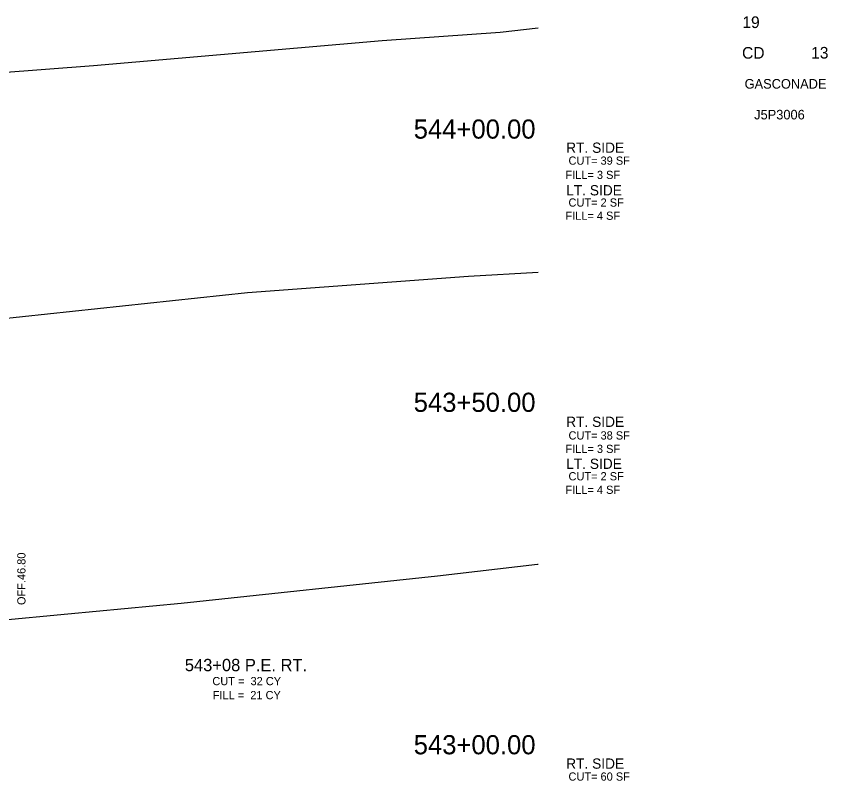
# Model space of a CAD drawing. Extents: x -4 to 359, y 0 to 1436.
# Drawn here: x 299.4 to 358.7, y 330.2 to 386.1 of the extents above; entities that cross this region are included whole.
import ezdxf

# ---------------------------------------------------------------- set-up
doc = ezdxf.new("R2010")
doc.units = 0
for name, color, linetype in [('Common-Title block info', 7, 'Continuous'), ('XS-Existing surface-ground', 7, 'Continuous'), ('XS-Text-earthwork labels', 7, 'Continuous'), ('XS-Text-offset label', 7, 'Continuous'), ('XS-Text-tie elevation', 7, 'Continuous')]:
    doc.layers.add(name, color=color, linetype=linetype)

msp = doc.modelspace()

# ---------------------------------------------------------------- linework, layer by layer
at = {"layer": 'XS-Existing surface-ground'}
for p, q in [((326.111, 384.307), (334.729, 384.919)), ((334.729, 384.919), (337.5, 385.239)), ((305.024, 382.476), (326.111, 384.307)), ((292.786, 381.565), (305.024, 382.476)), ((316.271, 365.902), (332.414, 367.082)), ((332.414, 367.082), (337.5, 367.373)), ((286.975, 362.784), (316.271, 365.902)), ((330.138, 345.194), (337.446, 346.064)), ((337.446, 346.064), (337.5, 346.068)), ((311.43, 343.207), (330.138, 345.194)), ((303.155, 342.431), (311.43, 343.207)), ((294.12, 341.584), (303.155, 342.431))]:
    msp.add_line(p, q, dxfattribs=at)

# ---------------------------------------------------------------- texts
at = {"layer": 'Common-Title block info'}
for s, height, p in [('19', 0.85, (352.417, 385.217)), ('CD', 0.85, (352.395, 382.979)), ('13', 0.85, (357.442, 382.988)), ('GASCONADE', 0.7, (352.581, 380.792)), ('J5P3006', 0.7, (353.279, 378.542))]:
    msp.add_text(s, height=height, dxfattribs=at).set_placement(p)
at = {"layer": 'XS-Text-earthwork labels'}
for s, height, p in [('RT. SIDE', 0.75, (339.547, 376.102)), (' CUT= 39 SF           ', 0.6, (339.495, 375.233)), ('FILL= 3 SF           ', 0.6, (339.495, 374.192)), ('LT. SIDE', 0.75, (339.547, 372.991)), (' CUT= 2 SF           ', 0.6, (339.495, 372.172)), ('FILL= 4 SF           ', 0.6, (339.495, 371.208)), ('RT. SIDE', 0.75, (339.547, 356.081)), (' CUT= 38 SF           ', 0.6, (339.495, 355.16)), ('FILL= 3 SF           ', 0.6, (339.495, 354.178)), ('LT. SIDE', 0.75, (339.547, 353.015)), (' CUT= 2 SF           ', 0.6, (339.495, 352.177)), ('FILL= 4 SF           ', 0.6, (339.495, 351.191)), ('543+08 P.E. RT.', 0.9, (311.692, 338.238)), ('CUT =  32 CY           ', 0.6, (313.703, 337.215)), ('FILL =  21 CY           ', 0.6, (313.729, 336.193)), ('RT. SIDE', 0.75, (339.547, 331.114)), (' CUT= 60 SF           ', 0.6, (339.495, 330.243))]:
    msp.add_text(s, height=height, dxfattribs=at).set_placement(p)
at = {"layer": 'XS-Text-offset label'}
for s, p in [('           544+00.00           ', (322.687, 377.139)), ('           543+50.00           ', (322.687, 357.18)), ('           543+00.00           ', (322.687, 332.168))]:
    msp.add_text(s, height=1.4, dxfattribs=at).set_placement(p)
at = {"layer": 'XS-Text-tie elevation'}
msp.add_text('OFF.46.80', height=0.6, rotation=90, dxfattribs=at).set_placement((300.051, 343.07))

doc.saveas('drawing.dxf')
